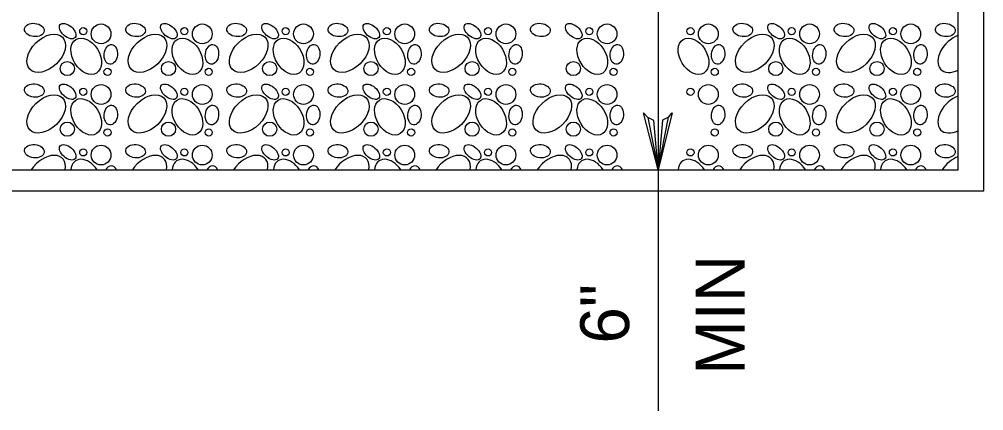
# Model space of a CAD drawing. Extents: x 636183 to 639890, y 299162 to 300538.
# Drawn here: x 637504.8 to 637564, y 299564.5 to 299588.5 of the extents above; entities that cross this region are included whole.
import ezdxf

# ---------------------------------------------------------------- set-up
doc = ezdxf.new("R2010")
doc.units = 0
doc.layers.add('Default', color=7, linetype='Continuous')

msp = doc.modelspace()

# ---------------------------------------------------------------- linework, layer by layer
at = {"layer": 'Default'}
for points in [[(637466.528, 299577.98), (637564, 299577.98), (637564, 299649.515), (637466.528, 299649.515)], [(637467.774, 299579.263), (637562.439, 299579.263), (637562.439, 299647.782), (637467.774, 299647.782)]]:
    msp.add_lwpolyline(points, close=True, dxfattribs=at)
for points in [[(637544.02, 299592.335), (637544.02, 299564.483)], [(637544.657, 299582.494), (637544.88, 299582.764), (637544.02, 299579.263), (637544.657, 299582.494), (637544.284, 299582.298), (637544.02, 299579.263), (637543.761, 299582.292), (637543.385, 299582.474), (637544.02, 299579.263), (637543.132, 299582.757), (637543.385, 299582.474)]]:
    msp.add_lwpolyline(points, dxfattribs=at)
for centre, radius in [((637508.742, 299587.766), 0.217), ((637509.836, 299587.603), 0.606), ((637514.952, 299587.766), 0.217), ((637516.047, 299587.603), 0.606), ((637521.163, 299587.766), 0.217), ((637522.258, 299587.603), 0.606), ((637527.374, 299587.766), 0.217), ((637528.469, 299587.603), 0.606), ((637533.585, 299587.766), 0.217), ((637534.68, 299587.603), 0.606), ((637539.796, 299587.766), 0.217), ((637540.891, 299587.603), 0.606), ((637546.007, 299587.766), 0.217), ((637547.102, 299587.603), 0.606), ((637552.218, 299587.766), 0.217), ((637553.313, 299587.603), 0.606), ((637558.429, 299587.766), 0.217), ((637559.524, 299587.603), 0.606), ((637507.764, 299585.473), 0.435), ((637513.975, 299585.473), 0.435), ((637520.186, 299585.473), 0.435), ((637526.397, 299585.473), 0.435), ((637532.608, 299585.473), 0.435), ((637538.819, 299585.473), 0.435), ((637551.241, 299585.473), 0.435), ((637557.452, 299585.473), 0.435), ((637510.233, 299585.272), 0.217), ((637516.444, 299585.272), 0.217), ((637522.655, 299585.272), 0.217), ((637528.866, 299585.272), 0.217), ((637535.077, 299585.272), 0.217), ((637541.288, 299585.272), 0.217), ((637547.498, 299585.272), 0.217), ((637553.709, 299585.272), 0.217), ((637559.92, 299585.272), 0.217), ((637509.836, 299583.884), 0.606), ((637516.047, 299583.884), 0.606), ((637522.258, 299583.884), 0.606), ((637528.469, 299583.884), 0.606), ((637534.68, 299583.884), 0.606), ((637540.891, 299583.884), 0.606), ((637547.102, 299583.884), 0.606), ((637553.313, 299583.884), 0.606), ((637559.524, 299583.884), 0.606), ((637508.742, 299584.047), 0.217), ((637514.952, 299584.047), 0.217), ((637521.163, 299584.047), 0.217), ((637527.374, 299584.047), 0.217), ((637533.585, 299584.047), 0.217), ((637539.796, 299584.047), 0.217), ((637546.007, 299584.047), 0.217), ((637552.218, 299584.047), 0.217), ((637558.429, 299584.047), 0.217), ((637507.764, 299581.754), 0.435), ((637513.975, 299581.754), 0.435), ((637520.186, 299581.754), 0.435), ((637526.397, 299581.754), 0.435), ((637532.608, 299581.754), 0.435), ((637538.819, 299581.754), 0.435), ((637551.241, 299581.754), 0.435), ((637557.452, 299581.754), 0.435), ((637510.233, 299581.553), 0.217), ((637516.444, 299581.553), 0.217), ((637522.655, 299581.553), 0.217), ((637528.866, 299581.553), 0.217), ((637535.077, 299581.553), 0.217), ((637541.288, 299581.553), 0.217), ((637547.498, 299581.553), 0.217), ((637553.709, 299581.553), 0.217), ((637559.92, 299581.553), 0.217), ((637508.742, 299580.328), 0.217), ((637509.836, 299580.165), 0.606), ((637514.952, 299580.328), 0.217), ((637516.047, 299580.165), 0.606), ((637521.163, 299580.328), 0.217), ((637522.258, 299580.165), 0.606), ((637527.374, 299580.328), 0.217), ((637528.469, 299580.165), 0.606), ((637533.585, 299580.328), 0.217), ((637534.68, 299580.165), 0.606), ((637539.796, 299580.328), 0.217), ((637540.891, 299580.165), 0.606), ((637546.007, 299580.328), 0.217), ((637547.102, 299580.165), 0.606), ((637552.218, 299580.328), 0.217), ((637553.313, 299580.165), 0.606), ((637558.429, 299580.328), 0.217), ((637559.524, 299580.165), 0.606)]:
    msp.add_circle(centre, radius, dxfattribs=at)
for centre, major_axis, ratio in [((637505.742, 299587.841), (0.603, -0.061), 0.672414), ((637507.789, 299587.77), (0.459, -0.397), 0.56568), ((637511.953, 299587.841), (0.603, -0.061), 0.672414), ((637514, 299587.77), (0.459, -0.397), 0.56568), ((637518.164, 299587.841), (0.603, -0.061), 0.672414), ((637520.211, 299587.77), (0.459, -0.397), 0.56568), ((637524.374, 299587.841), (0.603, -0.061), 0.672414), ((637526.422, 299587.77), (0.459, -0.397), 0.56568), ((637530.585, 299587.841), (0.603, -0.061), 0.672414), ((637532.633, 299587.77), (0.459, -0.397), 0.56568), ((637536.796, 299587.841), (0.603, -0.061), 0.672414), ((637538.844, 299587.77), (0.459, -0.397), 0.56568), ((637549.218, 299587.841), (0.603, -0.061), 0.672414), ((637551.266, 299587.77), (0.459, -0.397), 0.56568), ((637555.429, 299587.841), (0.603, -0.061), 0.672414), ((637557.477, 299587.77), (0.459, -0.397), 0.56568), ((637561.64, 299587.841), (0.603, -0.061), 0.672414), ((637506.473, 299586.412), (1.003, 0.982), 0.641702), ((637508.926, 299586.231), (-0.638, 1.03), 0.672414), ((637512.684, 299586.412), (1.003, 0.982), 0.641702), ((637515.137, 299586.231), (-0.638, 1.03), 0.672414), ((637518.895, 299586.412), (1.003, 0.982), 0.641702), ((637521.348, 299586.231), (-0.638, 1.03), 0.672414), ((637525.106, 299586.412), (1.003, 0.982), 0.641702), ((637527.559, 299586.231), (-0.638, 1.03), 0.672414), ((637531.317, 299586.412), (1.003, 0.982), 0.641702), ((637533.77, 299586.231), (-0.638, 1.03), 0.672414), ((637539.981, 299586.231), (-0.638, 1.03), 0.672414), ((637546.192, 299586.231), (-0.638, 1.03), 0.672414), ((637549.95, 299586.412), (1.003, 0.982), 0.641702), ((637552.403, 299586.231), (-0.638, 1.03), 0.672414), ((637556.161, 299586.412), (1.003, 0.982), 0.641702), ((637558.614, 299586.231), (-0.638, 1.03), 0.672414), ((637510.433, 299586.341), (0.061, 0.603), 0.672414), ((637516.644, 299586.341), (0.061, 0.603), 0.672414), ((637522.855, 299586.341), (0.061, 0.603), 0.672414), ((637529.066, 299586.341), (0.061, 0.603), 0.672414), ((637535.277, 299586.341), (0.061, 0.603), 0.672414), ((637541.488, 299586.341), (0.061, 0.603), 0.672414), ((637547.699, 299586.341), (0.061, 0.603), 0.672414), ((637553.91, 299586.341), (0.061, 0.603), 0.672414), ((637560.121, 299586.341), (0.061, 0.603), 0.672414), ((637505.742, 299584.122), (0.603, -0.061), 0.672414), ((637507.789, 299584.051), (0.459, -0.397), 0.56568), ((637511.953, 299584.122), (0.603, -0.061), 0.672414), ((637514, 299584.051), (0.459, -0.397), 0.56568), ((637518.164, 299584.122), (0.603, -0.061), 0.672414), ((637520.211, 299584.051), (0.459, -0.397), 0.56568), ((637524.374, 299584.122), (0.603, -0.061), 0.672414), ((637526.422, 299584.051), (0.459, -0.397), 0.56568), ((637530.585, 299584.122), (0.603, -0.061), 0.672414), ((637532.633, 299584.051), (0.459, -0.397), 0.56568), ((637536.796, 299584.122), (0.603, -0.061), 0.672414), ((637538.844, 299584.051), (0.459, -0.397), 0.56568), ((637549.218, 299584.122), (0.603, -0.061), 0.672414), ((637551.266, 299584.051), (0.459, -0.397), 0.56568), ((637555.429, 299584.122), (0.603, -0.061), 0.672414), ((637557.477, 299584.051), (0.459, -0.397), 0.56568), ((637561.64, 299584.122), (0.603, -0.061), 0.672414), ((637506.473, 299582.694), (1.003, 0.982), 0.641702), ((637508.926, 299582.512), (-0.638, 1.03), 0.672414), ((637512.684, 299582.694), (1.003, 0.982), 0.641702), ((637515.137, 299582.512), (-0.638, 1.03), 0.672414), ((637518.895, 299582.694), (1.003, 0.982), 0.641702), ((637521.348, 299582.512), (-0.638, 1.03), 0.672414), ((637525.106, 299582.694), (1.003, 0.982), 0.641702), ((637527.559, 299582.512), (-0.638, 1.03), 0.672414), ((637531.317, 299582.694), (1.003, 0.982), 0.641702), ((637533.77, 299582.512), (-0.638, 1.03), 0.672414), ((637537.528, 299582.694), (1.003, 0.982), 0.641702), ((637539.981, 299582.512), (-0.638, 1.03), 0.672414), ((637549.95, 299582.694), (1.003, 0.982), 0.641702), ((637552.403, 299582.512), (-0.638, 1.03), 0.672414), ((637556.161, 299582.694), (1.003, 0.982), 0.641702), ((637558.614, 299582.512), (-0.638, 1.03), 0.672414), ((637510.433, 299582.622), (0.061, 0.603), 0.672414), ((637516.644, 299582.622), (0.061, 0.603), 0.672414), ((637522.855, 299582.622), (0.061, 0.603), 0.672414), ((637529.066, 299582.622), (0.061, 0.603), 0.672414), ((637535.277, 299582.622), (0.061, 0.603), 0.672414), ((637541.488, 299582.622), (0.061, 0.603), 0.672414), ((637547.699, 299582.622), (0.061, 0.603), 0.672414), ((637553.91, 299582.622), (0.061, 0.603), 0.672414), ((637560.121, 299582.622), (0.061, 0.603), 0.672414), ((637505.742, 299580.403), (0.603, -0.061), 0.672414), ((637507.789, 299580.332), (0.459, -0.397), 0.56568), ((637511.953, 299580.403), (0.603, -0.061), 0.672414), ((637514, 299580.332), (0.459, -0.397), 0.56568), ((637518.164, 299580.403), (0.603, -0.061), 0.672414), ((637520.211, 299580.332), (0.459, -0.397), 0.56568), ((637524.374, 299580.403), (0.603, -0.061), 0.672414), ((637526.422, 299580.332), (0.459, -0.397), 0.56568), ((637530.585, 299580.403), (0.603, -0.061), 0.672414), ((637532.633, 299580.332), (0.459, -0.397), 0.56568), ((637536.796, 299580.403), (0.603, -0.061), 0.672414), ((637538.844, 299580.332), (0.459, -0.397), 0.56568), ((637549.218, 299580.403), (0.603, -0.061), 0.672414), ((637551.266, 299580.332), (0.459, -0.397), 0.56568), ((637555.429, 299580.403), (0.603, -0.061), 0.672414), ((637557.477, 299580.332), (0.459, -0.397), 0.56568), ((637561.64, 299580.403), (0.603, -0.061), 0.672414)]:
    msp.add_ellipse(centre, major_axis=major_axis, ratio=ratio, dxfattribs=at)
for centre, major_axis, ratio, start_param, end_param in [((637562.372, 299586.412), (1.003, 0.982), 0.641702, 0.953255, 4.207946), ((637562.372, 299582.694), (1.003, 0.982), 0.641702, 0.953255, 4.207946), ((637506.473, 299578.975), (1.003, 0.982), 0.641702, 5.540318, 8.186314), ((637508.926, 299578.793), (-0.638, 1.03), 0.672414, 4.752041, 7.024728), ((637512.684, 299578.975), (1.003, 0.982), 0.641702, 5.540318, 8.186314), ((637515.137, 299578.793), (-0.638, 1.03), 0.672414, 4.752041, 7.024728), ((637518.895, 299578.975), (1.003, 0.982), 0.641702, 5.540318, 8.186314), ((637521.348, 299578.793), (-0.638, 1.03), 0.672414, 4.752041, 7.024728), ((637525.106, 299578.975), (1.003, 0.982), 0.641702, 5.540318, 8.186314), ((637527.559, 299578.793), (-0.638, 1.03), 0.672414, 4.752041, 7.024728), ((637531.317, 299578.975), (1.003, 0.982), 0.641702, 5.540318, 8.186314), ((637533.77, 299578.793), (-0.638, 1.03), 0.672414, 4.752041, 7.024728), ((637537.528, 299578.975), (1.003, 0.982), 0.641702, 5.540318, 8.186314), ((637539.981, 299578.793), (-0.638, 1.03), 0.672414, 4.752041, 7.024728), ((637543.739, 299578.975), (1.003, 0.982), 0.641702, 0.726094, 0.804962), ((637546.192, 299578.793), (-0.638, 1.03), 0.672414, 4.752339, 7.0244), ((637549.95, 299578.975), (1.003, 0.982), 0.641702, 5.54051, 8.186086), ((637552.403, 299578.793), (-0.638, 1.03), 0.672414, 4.75222, 7.024518), ((637556.161, 299578.975), (1.003, 0.982), 0.641702, 5.540404, 8.186192), ((637558.614, 299578.793), (-0.638, 1.03), 0.672414, 4.752101, 7.024637), ((637562.372, 299578.975), (1.003, 0.982), 0.641702, 0.953255, 1.903112), ((637510.433, 299578.904), (0.061, 0.603), 0.672414, 5.416721, 7.285417), ((637516.644, 299578.904), (0.061, 0.603), 0.672414, 5.416721, 7.285417), ((637522.855, 299578.904), (0.061, 0.603), 0.672414, 5.416721, 7.285417), ((637529.066, 299578.904), (0.061, 0.603), 0.672414, 5.416721, 7.285417), ((637535.277, 299578.904), (0.061, 0.603), 0.672414, 5.416721, 7.285417), ((637541.488, 299578.904), (0.061, 0.603), 0.672414, 5.416721, 7.285417), ((637547.699, 299578.904), (0.061, 0.603), 0.672414, 5.417294, 7.284818), ((637553.91, 299578.904), (0.061, 0.603), 0.672414, 5.417047, 7.285065), ((637560.121, 299578.904), (0.061, 0.603), 0.672414, 5.4168, 7.285312)]:
    msp.add_ellipse(centre, major_axis=major_axis, ratio=ratio, start_param=start_param, end_param=end_param, dxfattribs=at)

# ---------------------------------------------------------------- texts
for s, p in [('MIN', (637549.326, 299566.688)), ('6"', (637542.241, 299568.604))]:
    msp.add_text(s, height=2.998, rotation=90, dxfattribs=at).set_placement(p)

doc.saveas('drawing.dxf')
